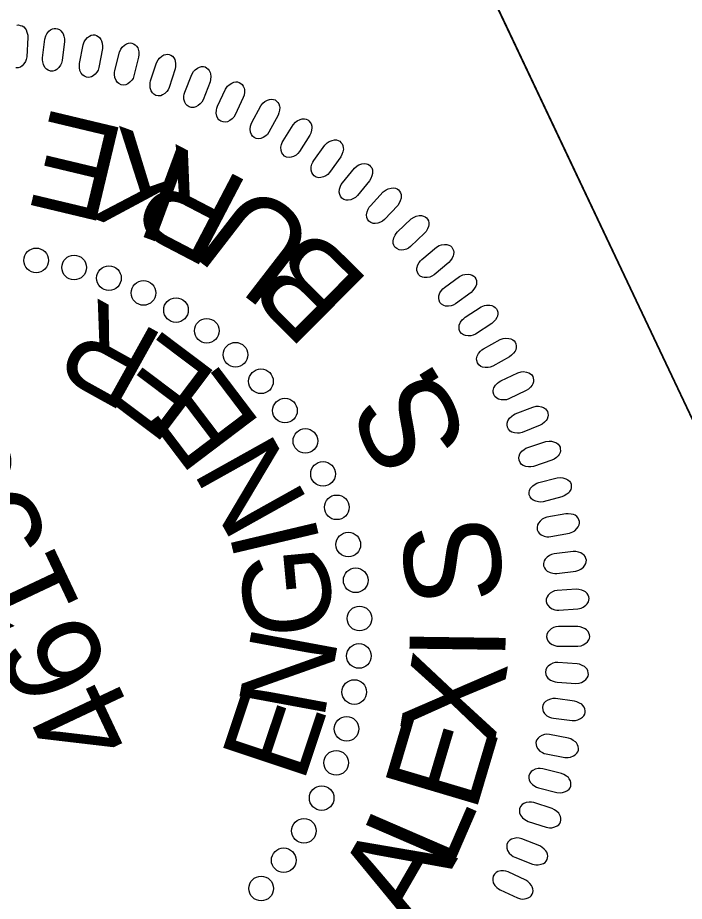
# Model space of a CAD drawing. Extents: x 476855 to 478565, y 498324 to 500313.
# Drawn here: x 476999.3 to 477042.6, y 499820.7 to 499878.2 of the extents above; entities that cross this region are included whole.
import ezdxf

# ---------------------------------------------------------------- set-up
doc = ezdxf.new("R2010")
doc.units = 0
for name, color, linetype in [('Sheet PE Seal Cell', 7, 'Continuous'), ('Sheet Plan CELL', 7, 'Continuous'), ('Sheet Sticker Exception Certification CELL', 7, 'Continuous'), ('Sheet Sticker Incomplete CELL', 7, 'Continuous')]:
    doc.layers.add(name, color=color, linetype=linetype)

msp = doc.modelspace()

# ---------------------------------------------------------------- linework, layer by layer
at = {"layer": 'Sheet PE Seal Cell'}
msp.add_lwpolyline([(476999.232, 499877.694), (476999.346, 499877.707), (476999.456, 499877.681), (476999.574, 499877.643), (476999.674, 499877.578), (476999.773, 499877.471), (476999.828, 499877.388), (476999.886, 499877.234), (476999.934, 499877.051), (476999.947, 499876.891), (476999.877, 499875.636), (476999.845, 499875.468), (476999.791, 499875.332), (476999.692, 499875.178), (476999.571, 499875.045), (476999.469, 499874.972), (476999.309, 499874.922), (476999.158, 499874.911)], dxfattribs=at)
for points in [[(477000.9, 499875.577), (477001.052, 499876.794), (477001.117, 499877.007), (477001.186, 499877.139), (477001.318, 499877.294), (477001.428, 499877.39), (477001.55, 499877.456), (477001.658, 499877.482), (477001.772, 499877.488), (477001.88, 499877.454), (477001.996, 499877.41), (477002.092, 499877.337), (477002.183, 499877.225), (477002.233, 499877.139), (477002.281, 499876.982), (477002.318, 499876.796), (477002.321, 499876.635), (477002.172, 499875.387), (477002.129, 499875.222), (477002.067, 499875.089), (477001.959, 499874.942), (477001.83, 499874.817), (477001.724, 499874.75), (477001.56, 499874.71), (477001.409, 499874.709), (477001.266, 499874.767), (477001.168, 499874.83), (477001.054, 499874.944), (477000.957, 499875.127), (477000.912, 499875.314), (477000.899, 499875.446)], [(477003.304, 499875.208), (477003.533, 499876.413), (477003.61, 499876.621), (477003.687, 499876.749), (477003.829, 499876.895), (477003.945, 499876.984), (477004.07, 499877.042), (477004.18, 499877.062), (477004.294, 499877.06), (477004.4, 499877.02), (477004.513, 499876.968), (477004.604, 499876.891), (477004.688, 499876.773), (477004.732, 499876.683), (477004.771, 499876.523), (477004.796, 499876.336), (477004.789, 499876.175), (477004.562, 499874.939), (477004.508, 499874.777), (477004.438, 499874.648), (477004.321, 499874.508), (477004.184, 499874.391), (477004.074, 499874.331), (477003.908, 499874.301), (477003.758, 499874.31), (477003.619, 499874.377), (477003.525, 499874.445), (477003.418, 499874.567), (477003.332, 499874.755), (477003.3, 499874.945), (477003.295, 499875.077)], [(477005.605, 499874.741), (477005.908, 499875.93), (477005.998, 499876.133), (477006.083, 499876.255), (477006.234, 499876.392), (477006.356, 499876.474), (477006.484, 499876.524), (477006.595, 499876.536), (477006.709, 499876.527), (477006.812, 499876.48), (477006.921, 499876.422), (477007.007, 499876.339), (477007.084, 499876.216), (477007.122, 499876.124), (477007.15, 499875.962), (477007.164, 499875.773), (477007.146, 499875.613), (477006.843, 499874.394), (477006.779, 499874.235), (477006.701, 499874.111), (477006.575, 499873.979), (477006.432, 499873.871), (477006.317, 499873.818), (477006.15, 499873.798), (477006.001, 499873.817), (477005.866, 499873.892), (477005.777, 499873.966), (477005.678, 499874.094), (477005.605, 499874.288), (477005.583, 499874.479), (477005.587, 499874.612)], [(477007.923, 499874.073), (477008.301, 499875.241), (477008.404, 499875.438), (477008.497, 499875.555), (477008.656, 499875.682), (477008.782, 499875.756), (477008.913, 499875.797), (477009.024, 499875.803), (477009.138, 499875.787), (477009.238, 499875.734), (477009.343, 499875.668), (477009.424, 499875.58), (477009.493, 499875.452), (477009.525, 499875.358), (477009.543, 499875.195), (477009.545, 499875.006), (477009.517, 499874.847), (477009.137, 499873.649), (477009.064, 499873.495), (477008.977, 499873.376), (477008.844, 499873.252), (477008.695, 499873.153), (477008.577, 499873.107), (477008.409, 499873.098), (477008.261, 499873.126), (477008.131, 499873.21), (477008.047, 499873.29), (477007.956, 499873.423), (477007.895, 499873.621), (477007.886, 499873.813), (477007.897, 499873.946)], [(477010.143, 499873.339), (477010.594, 499874.481), (477010.709, 499874.671), (477010.809, 499874.782), (477010.975, 499874.899), (477011.106, 499874.965), (477011.24, 499874.998), (477011.351, 499874.997), (477011.464, 499874.974), (477011.56, 499874.914), (477011.66, 499874.843), (477011.736, 499874.749), (477011.797, 499874.617), (477011.823, 499874.521), (477011.831, 499874.358), (477011.821, 499874.168), (477011.783, 499874.012), (477011.329, 499872.84), (477011.246, 499872.691), (477011.152, 499872.577), (477011.011, 499872.462), (477010.856, 499872.373), (477010.735, 499872.335), (477010.567, 499872.336), (477010.421, 499872.373), (477010.297, 499872.465), (477010.218, 499872.549), (477010.136, 499872.689), (477010.087, 499872.89), (477010.09, 499873.082), (477010.11, 499873.213)], [(477012.266, 499872.426), (477012.788, 499873.537), (477012.914, 499873.72), (477013.021, 499873.824), (477013.194, 499873.931), (477013.329, 499873.988), (477013.465, 499874.013), (477013.576, 499874.005), (477013.686, 499873.975), (477013.778, 499873.909), (477013.874, 499873.831), (477013.944, 499873.733), (477013.996, 499873.598), (477014.017, 499873.501), (477014.014, 499873.337), (477013.992, 499873.148), (477013.945, 499872.995), (477013.418, 499871.854), (477013.325, 499871.71), (477013.225, 499871.603), (477013.077, 499871.496), (477012.916, 499871.417), (477012.794, 499871.387), (477012.627, 499871.399), (477012.482, 499871.444), (477012.365, 499871.544), (477012.29, 499871.634), (477012.218, 499871.778), (477012.182, 499871.982), (477012.197, 499872.174), (477012.225, 499872.303)], [(477014.497, 499871.372), (477015.086, 499872.447), (477015.224, 499872.622), (477015.337, 499872.72), (477015.517, 499872.814), (477015.655, 499872.864), (477015.792, 499872.88), (477015.903, 499872.864), (477016.01, 499872.828), (477016.099, 499872.757), (477016.189, 499872.673), (477016.253, 499872.571), (477016.296, 499872.432), (477016.311, 499872.334), (477016.298, 499872.17), (477016.264, 499871.984), (477016.207, 499871.833), (477015.61, 499870.728), (477015.508, 499870.59), (477015.402, 499870.49), (477015.247, 499870.392), (477015.082, 499870.323), (477014.958, 499870.301), (477014.791, 499870.323), (477014.65, 499870.378), (477014.539, 499870.485), (477014.471, 499870.579), (477014.407, 499870.727), (477014.384, 499870.933), (477014.411, 499871.124), (477014.447, 499871.251)], [(477016.528, 499870.182), (477017.184, 499871.219), (477017.333, 499871.384), (477017.452, 499871.474), (477017.637, 499871.557), (477017.778, 499871.598), (477017.915, 499871.606), (477018.025, 499871.584), (477018.131, 499871.54), (477018.214, 499871.463), (477018.3, 499871.374), (477018.356, 499871.268), (477018.391, 499871.128), (477018.399, 499871.028), (477018.376, 499870.866), (477018.331, 499870.681), (477018.265, 499870.535), (477017.599, 499869.47), (477017.489, 499869.338), (477017.376, 499869.244), (477017.215, 499869.157), (477017.046, 499869.099), (477016.921, 499869.084), (477016.756, 499869.117), (477016.619, 499869.181), (477016.514, 499869.294), (477016.453, 499869.392), (477016.398, 499869.544), (477016.388, 499869.751), (477016.427, 499869.939), (477016.472, 499870.064)], [(477018.526, 499868.893), (477019.246, 499869.887), (477019.405, 499870.042), (477019.529, 499870.125), (477019.719, 499870.197), (477019.863, 499870.228), (477020, 499870.227), (477020.108, 499870.198), (477020.211, 499870.148), (477020.29, 499870.067), (477020.369, 499869.972), (477020.419, 499869.862), (477020.445, 499869.72), (477020.447, 499869.62), (477020.413, 499869.459), (477020.356, 499869.279), (477020.281, 499869.137), (477019.55, 499868.115), (477019.432, 499867.991), (477019.313, 499867.904), (477019.148, 499867.828), (477018.975, 499867.78), (477018.849, 499867.772), (477018.687, 499867.816), (477018.554, 499867.888), (477018.457, 499868.008), (477018.401, 499868.11), (477018.357, 499868.265), (477018.36, 499868.472), (477018.41, 499868.658), (477018.462, 499868.78)], [(477020.386, 499867.447), (477021.167, 499868.394), (477021.335, 499868.539), (477021.464, 499868.614), (477021.659, 499868.673), (477021.803, 499868.696), (477021.941, 499868.686), (477022.047, 499868.65), (477022.146, 499868.594), (477022.219, 499868.507), (477022.293, 499868.408), (477022.336, 499868.296), (477022.352, 499868.152), (477022.349, 499868.052), (477022.305, 499867.894), (477022.237, 499867.718), (477022.153, 499867.58), (477021.358, 499866.606), (477021.233, 499866.49), (477021.109, 499866.411), (477020.939, 499866.345), (477020.764, 499866.308), (477020.638, 499866.309), (477020.479, 499866.362), (477020.351, 499866.442), (477020.261, 499866.568), (477020.212, 499866.673), (477020.177, 499866.83), (477020.193, 499867.038), (477020.255, 499867.22), (477020.315, 499867.338)], [(477022.205, 499865.954), (477023.044, 499866.849), (477023.222, 499866.983), (477023.355, 499867.05), (477023.553, 499867.097), (477023.699, 499867.111), (477023.835, 499867.092), (477023.939, 499867.05), (477024.035, 499866.988), (477024.102, 499866.896), (477024.169, 499866.793), (477024.205, 499866.678), (477024.213, 499866.533), (477024.202, 499866.434), (477024.149, 499866.279), (477024.07, 499866.107), (477023.977, 499865.976), (477023.123, 499865.053), (477022.991, 499864.945), (477022.863, 499864.874), (477022.689, 499864.818), (477022.512, 499864.793), (477022.386, 499864.802), (477022.23, 499864.864), (477022.107, 499864.953), (477022.026, 499865.084), (477021.984, 499865.192), (477021.959, 499865.351), (477021.988, 499865.556), (477022.061, 499865.734), (477022.128, 499865.848)], [(477023.961, 499864.248), (477024.855, 499865.089), (477025.04, 499865.212), (477025.177, 499865.27), (477025.378, 499865.305), (477025.524, 499865.309), (477025.659, 499865.282), (477025.76, 499865.233), (477025.851, 499865.165), (477025.913, 499865.07), (477025.974, 499864.963), (477026.002, 499864.845), (477026.001, 499864.701), (477025.984, 499864.602), (477025.921, 499864.451), (477025.831, 499864.284), (477025.731, 499864.158), (477024.821, 499863.292), (477024.682, 499863.192), (477024.55, 499863.129), (477024.373, 499863.085), (477024.194, 499863.071), (477024.069, 499863.087), (477023.917, 499863.16), (477023.801, 499863.255), (477023.728, 499863.391), (477023.692, 499863.502), (477023.677, 499863.663), (477023.719, 499863.865), (477023.804, 499864.038), (477023.877, 499864.149)], [(477025.548, 499862.463), (477026.492, 499863.246), (477026.684, 499863.357), (477026.825, 499863.407), (477027.028, 499863.429), (477027.174, 499863.424), (477027.307, 499863.388), (477027.405, 499863.333), (477027.491, 499863.259), (477027.548, 499863.161), (477027.601, 499863.049), (477027.622, 499862.931), (477027.612, 499862.786), (477027.589, 499862.69), (477027.516, 499862.542), (477027.416, 499862.382), (477027.308, 499862.262), (477026.346, 499861.455), (477026.201, 499861.363), (477026.065, 499861.309), (477025.884, 499861.276), (477025.706, 499861.273), (477025.582, 499861.297), (477025.436, 499861.379), (477025.325, 499861.482), (477025.261, 499861.623), (477025.232, 499861.735), (477025.227, 499861.896), (477025.282, 499862.097), (477025.377, 499862.264), (477025.457, 499862.369)], [(477027.011, 499860.626), (477028.003, 499861.348), (477028.201, 499861.448), (477028.345, 499861.488), (477028.548, 499861.497), (477028.694, 499861.483), (477028.825, 499861.439), (477028.919, 499861.378), (477029.001, 499861.299), (477029.05, 499861.197), (477029.097, 499861.083), (477029.11, 499860.963), (477029.091, 499860.819), (477029.062, 499860.724), (477028.98, 499860.582), (477028.871, 499860.427), (477028.755, 499860.315), (477027.744, 499859.569), (477027.594, 499859.488), (477027.454, 499859.442), (477027.273, 499859.421), (477027.094, 499859.428), (477026.972, 499859.46), (477026.831, 499859.552), (477026.727, 499859.661), (477026.672, 499859.805), (477026.65, 499859.919), (477026.655, 499860.081), (477026.722, 499860.277), (477026.828, 499860.438), (477026.915, 499860.538)], [(477028.371, 499858.708), (477029.406, 499859.367), (477029.611, 499859.453), (477029.757, 499859.485), (477029.961, 499859.481), (477030.105, 499859.458), (477030.233, 499859.406), (477030.322, 499859.339), (477030.399, 499859.255), (477030.442, 499859.15), (477030.482, 499859.033), (477030.488, 499858.913), (477030.459, 499858.771), (477030.424, 499858.677), (477030.334, 499858.54), (477030.215, 499858.393), (477030.092, 499858.289), (477029.036, 499857.608), (477028.881, 499857.536), (477028.739, 499857.499), (477028.557, 499857.489), (477028.379, 499857.508), (477028.259, 499857.547), (477028.124, 499857.648), (477028.027, 499857.764), (477027.981, 499857.911), (477027.967, 499858.026), (477027.982, 499858.187), (477028.061, 499858.378), (477028.177, 499858.532), (477028.27, 499858.626)], [(477029.557, 499856.653), (477030.632, 499857.245), (477030.841, 499857.318), (477030.989, 499857.34), (477031.192, 499857.324), (477031.335, 499857.292), (477031.459, 499857.231), (477031.544, 499857.16), (477031.616, 499857.071), (477031.652, 499856.963), (477031.683, 499856.844), (477031.682, 499856.723), (477031.645, 499856.583), (477031.604, 499856.493), (477031.505, 499856.362), (477031.377, 499856.222), (477031.248, 499856.126), (477030.152, 499855.512), (477029.992, 499855.45), (477029.848, 499855.422), (477029.665, 499855.424), (477029.489, 499855.454), (477029.372, 499855.501), (477029.244, 499855.609), (477029.154, 499855.731), (477029.117, 499855.881), (477029.11, 499855.997), (477029.136, 499856.156), (477029.227, 499856.343), (477029.352, 499856.489), (477029.45, 499856.577)], [(477030.679, 499854.565), (477031.789, 499855.088), (477032.002, 499855.148), (477032.151, 499855.161), (477032.353, 499855.132), (477032.494, 499855.09), (477032.614, 499855.023), (477032.694, 499854.946), (477032.76, 499854.853), (477032.79, 499854.743), (477032.814, 499854.622), (477032.805, 499854.502), (477032.759, 499854.364), (477032.712, 499854.276), (477032.606, 499854.151), (477032.469, 499854.021), (477032.334, 499853.933), (477031.201, 499853.389), (477031.039, 499853.337), (477030.893, 499853.318), (477030.71, 499853.331), (477030.536, 499853.373), (477030.422, 499853.427), (477030.301, 499853.543), (477030.219, 499853.67), (477030.192, 499853.822), (477030.192, 499853.938), (477030.227, 499854.096), (477030.33, 499854.276), (477030.464, 499854.414), (477030.569, 499854.495)], [(477031.619, 499852.406), (477032.76, 499852.859), (477032.977, 499852.906), (477033.126, 499852.909), (477033.326, 499852.867), (477033.464, 499852.818), (477033.579, 499852.743), (477033.655, 499852.66), (477033.715, 499852.563), (477033.737, 499852.452), (477033.754, 499852.33), (477033.737, 499852.211), (477033.683, 499852.076), (477033.631, 499851.991), (477033.516, 499851.873), (477033.372, 499851.751), (477033.232, 499851.671), (477032.067, 499851.2), (477031.901, 499851.159), (477031.754, 499851.149), (477031.573, 499851.174), (477031.402, 499851.226), (477031.292, 499851.287), (477031.179, 499851.41), (477031.105, 499851.542), (477031.087, 499851.696), (477031.095, 499851.811), (477031.14, 499851.966), (477031.254, 499852.14), (477031.396, 499852.27), (477031.505, 499852.344)], [(477032.431, 499850.227), (477033.598, 499850.607), (477033.817, 499850.64), (477033.967, 499850.634), (477034.163, 499850.58), (477034.297, 499850.521), (477034.408, 499850.44), (477034.478, 499850.352), (477034.532, 499850.252), (477034.547, 499850.14), (477034.556, 499850.016), (477034.532, 499849.898), (477034.469, 499849.768), (477034.412, 499849.686), (477034.29, 499849.576), (477034.139, 499849.463), (477033.994, 499849.392), (477032.802, 499848.995), (477032.634, 499848.964), (477032.487, 499848.964), (477032.308, 499848.999), (477032.14, 499849.062), (477032.034, 499849.13), (477031.928, 499849.261), (477031.863, 499849.397), (477031.855, 499849.551), (477031.87, 499849.666), (477031.925, 499849.818), (477032.049, 499849.983), (477032.199, 499850.104), (477032.313, 499850.172)], [(477033.147, 499847.948), (477034.335, 499848.255), (477034.557, 499848.274), (477034.705, 499848.258), (477034.898, 499848.192), (477035.028, 499848.125), (477035.133, 499848.036), (477035.198, 499847.945), (477035.245, 499847.841), (477035.254, 499847.728), (477035.255, 499847.605), (477035.223, 499847.488), (477035.153, 499847.362), (477035.09, 499847.284), (477034.962, 499847.182), (477034.803, 499847.079), (477034.654, 499847.017), (477033.44, 499846.696), (477033.27, 499846.675), (477033.123, 499846.684), (477032.947, 499846.731), (477032.783, 499846.805), (477032.682, 499846.879), (477032.585, 499847.015), (477032.528, 499847.156), (477032.53, 499847.31), (477032.552, 499847.424), (477032.616, 499847.572), (477032.75, 499847.73), (477032.908, 499847.84), (477033.025, 499847.901)], [(477033.94, 499844.428), (477035.145, 499844.659), (477035.352, 499844.737), (477035.48, 499844.814), (477035.626, 499844.957), (477035.715, 499845.073), (477035.772, 499845.198), (477035.792, 499845.308), (477035.79, 499845.422), (477035.749, 499845.528), (477035.697, 499845.64), (477035.619, 499845.732), (477035.501, 499845.815), (477035.412, 499845.86), (477035.252, 499845.897), (477035.064, 499845.922), (477034.903, 499845.914), (477033.668, 499845.685), (477033.506, 499845.63), (477033.377, 499845.559), (477033.237, 499845.441), (477033.121, 499845.305), (477033.062, 499845.195), (477033.032, 499845.029), (477033.041, 499844.879), (477033.109, 499844.739), (477033.177, 499844.646), (477033.299, 499844.54), (477033.488, 499844.455), (477033.677, 499844.422), (477033.81, 499844.418)], [(477034.328, 499842.031), (477035.545, 499842.186), (477035.758, 499842.251), (477035.89, 499842.32), (477036.044, 499842.453), (477036.141, 499842.563), (477036.205, 499842.685), (477036.232, 499842.793), (477036.237, 499842.907), (477036.203, 499843.016), (477036.158, 499843.131), (477036.086, 499843.227), (477035.973, 499843.318), (477035.887, 499843.367), (477035.73, 499843.415), (477035.544, 499843.452), (477035.383, 499843.454), (477034.136, 499843.302), (477033.97, 499843.258), (477033.838, 499843.196), (477033.691, 499843.087), (477033.567, 499842.958), (477033.5, 499842.851), (477033.46, 499842.689), (477033.459, 499842.537), (477033.518, 499842.394), (477033.581, 499842.297), (477033.695, 499842.183), (477033.878, 499842.087), (477034.066, 499842.042), (477034.198, 499842.029)], [(477034.456, 499839.648), (477035.68, 499839.727), (477035.897, 499839.778), (477036.033, 499839.839), (477036.195, 499839.962), (477036.299, 499840.066), (477036.371, 499840.183), (477036.404, 499840.29), (477036.417, 499840.404), (477036.39, 499840.513), (477036.352, 499840.631), (477036.286, 499840.732), (477036.179, 499840.83), (477036.096, 499840.885), (477035.942, 499840.942), (477035.76, 499840.99), (477035.599, 499841.003), (477034.344, 499840.929), (477034.177, 499840.896), (477034.04, 499840.842), (477033.887, 499840.743), (477033.754, 499840.622), (477033.681, 499840.519), (477033.631, 499840.359), (477033.621, 499840.208), (477033.671, 499840.062), (477033.727, 499839.961), (477033.835, 499839.84), (477034.012, 499839.732), (477034.195, 499839.676), (477034.326, 499839.655)], [(477034.454, 499837.294), (477035.68, 499837.296), (477035.899, 499837.333), (477036.039, 499837.386), (477036.209, 499837.498), (477036.318, 499837.595), (477036.398, 499837.708), (477036.438, 499837.812), (477036.457, 499837.925), (477036.437, 499838.036), (477036.407, 499838.156), (477036.347, 499838.26), (477036.247, 499838.365), (477036.168, 499838.425), (477036.018, 499838.492), (477035.838, 499838.552), (477035.679, 499838.574), (477034.422, 499838.58), (477034.252, 499838.557), (477034.113, 499838.511), (477033.953, 499838.422), (477033.814, 499838.31), (477033.734, 499838.212), (477033.675, 499838.055), (477033.655, 499837.905), (477033.695, 499837.757), (477033.745, 499837.651), (477033.845, 499837.525), (477034.014, 499837.406), (477034.195, 499837.339), (477034.324, 499837.309)], [(477034.333, 499834.959), (477035.557, 499834.884), (477035.779, 499834.908), (477035.922, 499834.951), (477036.098, 499835.053), (477036.213, 499835.143), (477036.3, 499835.25), (477036.346, 499835.352), (477036.373, 499835.463), (477036.36, 499835.575), (477036.337, 499835.697), (477036.284, 499835.805), (477036.191, 499835.915), (477036.115, 499835.98), (477035.97, 499836.057), (477035.794, 499836.127), (477035.636, 499836.16), (477034.382, 499836.244), (477034.212, 499836.232), (477034.07, 499836.196), (477033.905, 499836.116), (477033.759, 499836.013), (477033.673, 499835.921), (477033.604, 499835.768), (477033.575, 499835.62), (477033.605, 499835.468), (477033.649, 499835.361), (477033.74, 499835.228), (477033.902, 499835.098), (477034.077, 499835.019), (477034.204, 499834.982)], [(477034.096, 499832.615), (477035.314, 499832.464), (477035.536, 499832.473), (477035.681, 499832.507), (477035.864, 499832.598), (477035.984, 499832.681), (477036.077, 499832.782), (477036.13, 499832.881), (477036.163, 499832.99), (477036.158, 499833.103), (477036.143, 499833.226), (477036.096, 499833.337), (477036.011, 499833.453), (477035.938, 499833.523), (477035.799, 499833.608), (477035.628, 499833.689), (477035.472, 499833.732), (477034.227, 499833.895), (477034.055, 499833.893), (477033.911, 499833.866), (477033.742, 499833.797), (477033.589, 499833.703), (477033.498, 499833.616), (477033.419, 499833.468), (477033.381, 499833.322), (477033.402, 499833.169), (477033.439, 499833.059), (477033.521, 499832.92), (477033.675, 499832.781), (477033.845, 499832.692), (477033.97, 499832.646)], [(477033.631, 499830.292), (477034.837, 499830.064), (477035.059, 499830.06), (477035.206, 499830.085), (477035.394, 499830.164), (477035.52, 499830.239), (477035.619, 499830.335), (477035.678, 499830.43), (477035.718, 499830.536), (477035.719, 499830.65), (477035.712, 499830.773), (477035.673, 499830.887), (477035.594, 499831.009), (477035.527, 499831.082), (477035.392, 499831.176), (477035.227, 499831.268), (477035.075, 499831.32), (477033.842, 499831.561), (477033.671, 499831.571), (477033.525, 499831.552), (477033.352, 499831.494), (477033.193, 499831.41), (477033.097, 499831.329), (477033.009, 499831.186), (477032.961, 499831.043), (477032.973, 499830.888), (477033.003, 499830.777), (477033.076, 499830.633), (477033.221, 499830.485), (477033.385, 499830.384), (477033.507, 499830.331)], [(477033.126, 499828.084), (477034.315, 499827.78), (477034.537, 499827.762), (477034.685, 499827.778), (477034.877, 499827.845), (477035.007, 499827.912), (477035.112, 499828.001), (477035.177, 499828.092), (477035.224, 499828.196), (477035.232, 499828.309), (477035.233, 499828.432), (477035.201, 499828.548), (477035.129, 499828.675), (477035.068, 499828.753), (477034.939, 499828.855), (477034.78, 499828.957), (477034.631, 499829.019), (477033.415, 499829.336), (477033.245, 499829.357), (477033.099, 499829.347), (477032.922, 499829.3), (477032.759, 499829.227), (477032.657, 499829.152), (477032.561, 499829.014), (477032.505, 499828.874), (477032.507, 499828.72), (477032.529, 499828.606), (477032.594, 499828.458), (477032.729, 499828.301), (477032.886, 499828.19), (477033.004, 499828.13)], [(477032.464, 499825.902), (477033.632, 499825.524), (477033.852, 499825.492), (477034.001, 499825.499), (477034.197, 499825.553), (477034.332, 499825.612), (477034.442, 499825.694), (477034.511, 499825.781), (477034.565, 499825.882), (477034.58, 499825.995), (477034.589, 499826.118), (477034.565, 499826.236), (477034.501, 499826.366), (477034.444, 499826.447), (477034.322, 499826.558), (477034.17, 499826.67), (477034.025, 499826.741), (477032.832, 499827.134), (477032.664, 499827.165), (477032.517, 499827.165), (477032.337, 499827.129), (477032.171, 499827.066), (477032.065, 499826.998), (477031.959, 499826.867), (477031.894, 499826.73), (477031.886, 499826.576), (477031.902, 499826.461), (477031.957, 499826.309), (477032.082, 499826.144), (477032.232, 499826.024), (477032.346, 499825.956)], [(477031.598, 499823.573), (477032.74, 499823.123), (477032.957, 499823.077), (477033.106, 499823.074), (477033.305, 499823.116), (477033.443, 499823.167), (477033.558, 499823.242), (477033.634, 499823.325), (477033.693, 499823.422), (477033.716, 499823.533), (477033.732, 499823.656), (477033.715, 499823.774), (477033.66, 499823.909), (477033.608, 499823.993), (477033.493, 499824.111), (477033.348, 499824.233), (477033.209, 499824.312), (477032.042, 499824.78), (477031.876, 499824.822), (477031.73, 499824.83), (477031.549, 499824.806), (477031.378, 499824.753), (477031.268, 499824.692), (477031.154, 499824.568), (477031.081, 499824.436), (477031.063, 499824.282), (477031.071, 499824.166), (477031.117, 499824.012), (477031.231, 499823.838), (477031.374, 499823.709), (477031.483, 499823.635)], [(477030.643, 499821.451), (477031.754, 499820.93), (477031.967, 499820.871), (477032.116, 499820.859), (477032.317, 499820.888), (477032.458, 499820.93), (477032.578, 499820.998), (477032.658, 499821.075), (477032.724, 499821.169), (477032.753, 499821.278), (477032.777, 499821.4), (477032.768, 499821.519), (477032.721, 499821.656), (477032.675, 499821.745), (477032.568, 499821.869), (477032.431, 499821.999), (477032.296, 499822.088), (477031.161, 499822.628), (477030.998, 499822.68), (477030.853, 499822.698), (477030.671, 499822.684), (477030.496, 499822.643), (477030.383, 499822.589), (477030.262, 499822.472), (477030.18, 499822.345), (477030.153, 499822.193), (477030.154, 499822.077), (477030.19, 499821.919), (477030.292, 499821.739), (477030.427, 499821.601), (477030.532, 499821.52)]]:
    msp.add_lwpolyline(points, close=True, dxfattribs=at)
for centre in [(477000.486, 499862.398), (477002.952, 499861.934), (477005.217, 499861.242), (477007.46, 499860.279), (477009.573, 499859.163), (477011.573, 499857.818), (477013.44, 499856.26), (477015.094, 499854.531), (477016.654, 499852.626), (477017.981, 499850.655), (477019.126, 499848.51), (477020.021, 499846.335), (477020.768, 499843.914), (477021.25, 499841.588), (477021.496, 499839.106), (477021.458, 499836.667), (477021.155, 499834.322), (477020.656, 499831.929), (477019.982, 499829.718), (477019.038, 499827.423), (477017.885, 499825.294), (477016.573, 499823.381), (477015.106, 499821.543)]:
    msp.add_circle(centre, 0.801, dxfattribs=at)
at = {"layer": 'Sheet Plan CELL'}
for points in [[(478473.171, 498932.305), (477523.837, 498483.654), (476968.372, 499659.005), (477104.041, 499723.121), (477018.584, 499903.986), (477832.243, 500288.494)], [(476959.595, 499765.507), (476916.863, 499855.903), (477018.584, 499903.986), (477061.321, 499813.579)]]:
    msp.add_lwpolyline(points, close=True, dxfattribs=at)
at = {"layer": 'Sheet Sticker Exception Certification CELL'}
msp.add_line((477104.041, 499723.121), (477018.572, 499903.981), dxfattribs=at)
msp.add_line((477104.041, 499723.121), (477018.572, 499903.981), dxfattribs=at)

# ---------------------------------------------------------------- texts
at = {"layer": 'Sheet PE Seal Cell'}
for s, height, rotation, p in [('E', 6.236, 166.56206, (477006.495, 499870.892)), ('K', 6.236, 159.7164, (477011.001, 499869.255)), ('R', 6.236, 152.44138, (477014.545, 499867.356)), ('U', 6.236, 142.34153, (477019.052, 499864.061)), ('B', 6.236, 135.22469, (477022.285, 499860.922)), ('R', 5.669, 150.95736, (477008.96, 499857.424)), ('E', 5.669, 143.01757, (477012.44, 499854.887)), ('E', 5.669, 127.13797, (477015.194, 499851.687)), ('.', 6.236, 121.52207, (477027.034, 499854.139)), ('S', 6.236, 114.67642, (477028.716, 499850.467)), ('46155', 6.2363, 115.27516, (477007.439, 499831.425)), ('N', 5.669, 119.19818, (477018.241, 499846.659)), ('I', 5.669, 103.31858, (477018.99, 499843.967)), ('S', 6.236, 96.08122, (477030.94, 499840.323)), ('G', 5.669, 95.37878, (477019.868, 499838.157)), ('N', 5.669, 79.49919, (477019.157, 499832.408)), ('I', 6.236, 89.23556, (477030.97, 499836.294)), ('X', 6.236, 80.28824, (477030.233, 499830.693)), ('E', 5.669, 71.55939, (477017.825, 499828.311)), ('E', 6.236, 73.44258, (477028.998, 499826.348)), ('L', 6.236, 66.59692, (477027.371, 499822.578)), ('A', 6.236, 59.97725, (477025.129, 499818.709))]:
    msp.add_text(s, height=height, rotation=rotation, dxfattribs=at).set_placement(p)
at = {"layer": 'Sheet Sticker Incomplete CELL'}
for s, height, p in [('INCOMPLETE PLANS', 11.52, (477027.454, 499726.18)), ('DO NOT USE FOR R/W ACQUISITION', 5.76, (477032.349, 499732.088))]:
    msp.add_text(s, height=height, rotation=115.2938, dxfattribs=at).set_placement(p)

doc.saveas('drawing.dxf')
